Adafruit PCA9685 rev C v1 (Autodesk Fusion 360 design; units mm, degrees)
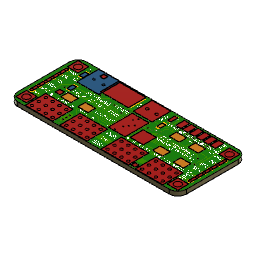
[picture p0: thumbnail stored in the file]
part number: PCA9685
part number: 10K
part number: MOUNTINGHOLE2.5
part number: FIDUCIAL""
part number: AOD417
part number: GREEN
part number: 470
pcb "PCB1" BoardHeight 1.57
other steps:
extrude "Extrude1" new body sketch "Sketch1" along normal blind 1.57 bodies "Board"
extrude "Extrude1" new body sketch "Sketch1" along normal blind 0.1 bodies "TSSOP28"
extrude "Extrude1" new body sketch "Sketch1" along normal blind 0.1 bodies "SOLDERJUMPER_REFLOW_NOPASTE"
extrude "Extrude1" new body sketch "Sketch1" along normal blind 0.1 bodies "0805-NO"
extrude "Extrude1" new body sketch "Sketch1" along normal blind 0.1 bodies "TERMBLOCK_1X2-3.5MM"
extrude "Extrude1" new body sketch "Sketch1" along normal blind 0.1 bodies "MOUNTINGHOLE_2.5_PLATED"
extrude "Extrude1" new body sketch "Sketch1" along normal blind 0.1 bodies "FIDUCIAL_1MM"
extrude "Extrude1" new body sketch "Sketch1" along normal blind 0.1 bodies "TO252"
extrude "Extrude1" new body sketch "Sketch1" along normal blind 0.1 bodies "CHIPLED_0805_NOOUTLINE"
extrude "Extrude1" new body sketch "Sketch1" along normal blind 0.1 bodies "_0805MP"
extrude "Extrude1" new body sketch "Sketch1" along normal blind 0.1 bodies "E3,5-8"
extrude "Extrude1" new body sketch "Sketch1" along normal blind 0.1 bodies "ADAFRUIT_5MM"
extrude "Extrude1" new body sketch "Sketch1" along normal blind 0.1 bodies "1X06-CLEANBIG"
extrude "Extrude1" new body sketch "Sketch1" along normal blind 0.1 bodies "3X04"
extrude "Extrude1" new body sketch "Sketch1" along normal blind 0.1 bodies "RESPACK_4X0603"
extrude "Extrude1" new body sketch "Sketch1" along normal blind 0.1 bodies "PCBFEAT-REV-040"
extrude "Extrude1" new body sketch "Sketch1" along normal blind 0.1 bodies "TESTPOINT_ROUND_1MM"
extrude "Extrude2" sketch "Sketch2" blind 1.57
create_component "CreateComponent1"
create_component "CreateComponent1"
sketch "Sketch1" plane through (0, 0, 0) normal (0, 0, 1) x axis (1, 0, 0)
  line L1 (-1.905, 15.748) -> (-1.905, -3.302)
  line L2 (57.15, 18.923) -> (1.27, 18.923)
  line L3 (60.325, -3.302) -> (60.325, 15.748)
  line L4 (1.27, -6.477) -> (57.15, -6.477)
  arc A1 centre (1.27, -3.302) radius 3.175 clockwise from (1.27, -6.477) to (-1.905, -3.302)
  arc A2 centre (1.27, 15.748) radius 3.175 clockwise from (-1.905, 15.748) to (1.27, 18.923)
  arc A3 centre (57.15, 15.748) radius 3.175 clockwise from (57.15, 18.923) to (60.325, 15.748)
  arc A4 centre (57.15, -3.302) radius 3.175 clockwise from (60.325, -3.302) to (57.15, -6.477)
canvas "Canvas1"
canvas "Canvas2"
sketch "Sketch2" plane through (0, 0, 0) normal (0, 0, 1) x axis (1, 0, 0)
  circle C1 centre (15.24, -2.54) radius 0.25
  circle C2 centre (15.24, -1.27) radius 0.25
  circle C3 centre (15.24, -3.81) radius 0.25
  circle C4 centre (4.953, 16.637) radius 0.197
  circle C5 centre (27.94, 2.667) radius 0.197
  circle C6 centre (33.655, 9.144) radius 0.197
  circle C7 centre (46.482, 13.081) radius 0.197
  circle C8 centre (5.334, 6.731) radius 0.197
  circle C9 centre (50.419, 14.224) radius 0.197
  circle C10 centre (29.083, 10.16) radius 0.197
  circle C11 centre (47.879, 14.224) radius 0.197
  circle C12 centre (24.765, 10.922) radius 0.197
  circle C13 centre (45.339, 14.224) radius 0.197
  circle C14 centre (22.86, 10.795) radius 0.197
  circle C15 centre (42.799, 14.224) radius 0.197
  circle C16 centre (23.876, 9.017) radius 0.197
  circle C17 centre (40.259, 14.224) radius 0.197
  circle C18 centre (20.193, 10.287) radius 0.197
  circle C19 centre (38.989, 14.605) radius 0.197
  circle C20 centre (15.367, 11.811) radius 0.197
  circle C21 centre (30.48, 7.493) radius 0.197
  circle C22 centre (29.464, 6.223) radius 0.197
  circle C23 centre (14.478, 10.795) radius 0.197
  circle C24 centre (52.578, 8.636) radius 0.197
  circle C25 centre (28.575, 5.08) radius 0.197
  circle C26 centre (28.321, 9.017) radius 0.197
  circle C27 centre (53.848, 6.096) radius 0.197
  circle C28 centre (27.41, 15.113) radius 0.5
  circle C29 centre (30.91, 15.113) radius 0.5
  circle C30 centre (1.27, 15.748) radius 1.25
  circle C31 centre (1.27, -3.302) radius 1.25
  circle C32 centre (57.15, 15.748) radius 1.25
  circle C33 centre (57.15, -3.302) radius 1.25
  circle C34 centre (8.128, 14.732) radius 0.4065
  circle C35 centre (11.684, 14.732) radius 0.4065
  circle C36 centre (0, 0) radius 0.508
  circle C37 centre (0, 2.54) radius 0.508
  circle C38 centre (0, 5.08) radius 0.508
  circle C39 centre (0, 7.62) radius 0.508
  circle C40 centre (0, 10.16) radius 0.508
  circle C41 centre (0, 12.7) radius 0.508
  circle C42 centre (58.42, 0) radius 0.508
  circle C43 centre (58.42, 2.54) radius 0.508
  circle C44 centre (58.42, 5.08) radius 0.508
  circle C45 centre (58.42, 7.62) radius 0.508
  circle C46 centre (58.42, 10.16) radius 0.508
  circle C47 centre (58.42, 12.7) radius 0.508
  circle C48 centre (25.4, 0) radius 0.5
  circle C49 centre (25.4, -2.54) radius 0.5
  circle C50 centre (22.86, 0) radius 0.5
  circle C51 centre (22.86, -2.54) radius 0.5
  circle C52 centre (20.32, 0) radius 0.5
  circle C53 centre (20.32, -2.54) radius 0.5
  circle C54 centre (17.78, 0) radius 0.5
  circle C55 centre (17.78, -2.54) radius 0.5
  circle C56 centre (25.4, -5.08) radius 0.5
  circle C57 centre (22.86, -5.08) radius 0.5
  circle C58 centre (20.32, -5.08) radius 0.5
  circle C59 centre (17.78, -5.08) radius 0.5
  circle C60 centre (12.7, 0) radius 0.5
  circle C61 centre (12.7, -2.54) radius 0.5
  circle C62 centre (10.16, 0) radius 0.5
  circle C63 centre (10.16, -2.54) radius 0.5
  circle C64 centre (7.62, 0) radius 0.5
  circle C65 centre (7.62, -2.54) radius 0.5
  circle C66 centre (5.08, 0) radius 0.5
  circle C67 centre (5.08, -2.54) radius 0.5
  circle C68 centre (12.7, -5.08) radius 0.5
  circle C69 centre (10.16, -5.08) radius 0.5
  circle C70 centre (7.62, -5.08) radius 0.5
  circle C71 centre (5.08, -5.08) radius 0.5
  circle C72 centre (53.34, 0) radius 0.5
  circle C73 centre (53.34, -2.54) radius 0.5
  circle C74 centre (50.8, 0) radius 0.5
  circle C75 centre (50.8, -2.54) radius 0.5
  circle C76 centre (48.26, 0) radius 0.5
  circle C77 centre (48.26, -2.54) radius 0.5
  circle C78 centre (45.72, 0) radius 0.5
  circle C79 centre (45.72, -2.54) radius 0.5
  circle C80 centre (53.34, -5.08) radius 0.5
  circle C81 centre (50.8, -5.08) radius 0.5
  circle C82 centre (48.26, -5.08) radius 0.5
  circle C83 centre (45.72, -5.08) radius 0.5
  circle C84 centre (40.64, 0) radius 0.5
  circle C85 centre (40.64, -2.54) radius 0.5
  circle C86 centre (38.1, 0) radius 0.5
  circle C87 centre (38.1, -2.54) radius 0.5
  circle C88 centre (35.56, 0) radius 0.5
  circle C89 centre (35.56, -2.54) radius 0.5
  circle C90 centre (33.02, 0) radius 0.5
  circle C91 centre (33.02, -2.54) radius 0.5
  circle C92 centre (40.64, -5.08) radius 0.5
  circle C93 centre (38.1, -5.08) radius 0.5
  circle C94 centre (35.56, -5.08) radius 0.5
  circle C95 centre (33.02, -5.08) radius 0.5
create_component "CreateComponent2" sketch "Sketch1"
sketch "Sketch1" plane through (0, 0, 0) normal (0, 0, 1) x axis (1, 0, 0)
  line L1 (4.465, -3.121) -> (-4.465, -3.121)
  line L2 (4.465, 3.121) -> (4.465, -3.121)
  line L3 (-4.465, 3.121) -> (4.465, 3.121)
  line L4 (-4.465, -3.121) -> (-4.465, 3.121)
create_component "CreateComponent3" sketch "Sketch1"
sketch "Sketch1" plane through (0, 0, 0) normal (0, 0, 1) x axis (1, 0, 0)
  line L1 (1.651, -1.016) -> (-1.651, -1.016)
  line L2 (1.651, 1.016) -> (1.651, -1.016)
  line L3 (-1.651, 1.016) -> (1.651, 1.016)
  line L4 (-1.651, -1.016) -> (-1.651, 1.016)
create_component "CreateComponent4" sketch "Sketch1"
sketch "Sketch1" plane through (0, 0, 0) normal (0, 0, 1) x axis (1, 0, 0)
  line L1 (1.106, -0.724) -> (-1.092, -0.724)
  line L2 (1.106, 0.726) -> (1.106, -0.724)
  line L3 (-1.092, 0.726) -> (1.106, 0.726)
  line L4 (-1.092, -0.724) -> (-1.092, 0.726)
create_component "CreateComponent5" sketch "Sketch1"
sketch "Sketch1" plane through (0, 0, 0) normal (0, 0, 1) x axis (1, 0, 0)
  line L1 (3.6, -3.6) -> (-3.4, -3.6)
  line L2 (3.6, 3.4) -> (3.6, -3.6)
  line L3 (-3.4, 3.4) -> (3.6, 3.4)
  line L4 (-3.4, -3.6) -> (-3.4, 3.4)
create_component "CreateComponent6" sketch "Sketch1"
sketch "Sketch1" plane through (0, 0, 0) normal (0, 0, 1) x axis (1, 0, 0)
  line L1 (2, -2) -> (-2, -2)
  line L2 (2, 2) -> (2, -2)
  line L3 (-2, 2) -> (2, 2)
  line L4 (-2, -2) -> (-2, 2)
create_component "CreateComponent7" sketch "Sketch1"
sketch "Sketch1" plane through (0, 0, 0) normal (0, 0, 1) x axis (1, 0, 0)
  line L1 (0.75, -0.75) -> (-0.75, -0.75)
  line L2 (0.75, 0.75) -> (0.75, -0.75)
  line L3 (-0.75, 0.75) -> (0.75, 0.75)
  line L4 (-0.75, -0.75) -> (-0.75, 0.75)
create_component "CreateComponent8" sketch "Sketch1"
sketch "Sketch1" plane through (0, 0, 0) normal (0, 0, 1) x axis (1, 0, 0)
  line L1 (3.277, -5.156) -> (-3.277, -5.156)
  line L2 (3.277, 5.105) -> (3.277, -5.156)
  line L3 (-3.277, 5.105) -> (3.277, 5.105)
  line L4 (-3.277, -5.156) -> (-3.277, 5.105)
create_component "CreateComponent9" sketch "Sketch1"
sketch "Sketch1" plane through (0, 0, 0) normal (0, 0, 1) x axis (1, 0, 0)
  line L1 (0.625, -1.3334) -> (-0.625, -1.3334)
  line L2 (0.625, 1.3334) -> (0.625, -1.3334)
  line L3 (-0.625, 1.3334) -> (0.625, 1.3334)
  line L4 (-0.625, -1.3334) -> (-0.625, 1.3334)
create_component "CreateComponent10" sketch "Sketch1"
sketch "Sketch1" plane through (0, 0, 0) normal (0, 0, 1) x axis (1, 0, 0)
  line L1 (1, -0.65) -> (-1, -0.65)
  line L2 (1, 0.65) -> (1, -0.65)
  line L3 (-1, 0.65) -> (1, 0.65)
  line L4 (-1, -0.65) -> (-1, 0.65)
create_component "CreateComponent11" sketch "Sketch1"
sketch "Sketch1" plane through (0, 0, 0) normal (0, 0, 1) x axis (1, 0, 0)
  line L1 (4.064, -4.064) -> (-4.064, -4.064)
  line L2 (4.064, 4.064) -> (4.064, -4.064)
  line L3 (-4.064, 4.064) -> (4.064, 4.064)
  line L4 (-4.064, -4.064) -> (-4.064, 4.064)
create_component "CreateComponent12" sketch "Sketch1"
sketch "Sketch1" plane through (0, 0, 0) normal (0, 0, 1) x axis (1, 0, 0)
  line L1 (4.873, -0.004) -> (-0.004, -0.004)
  line L2 (4.873, 4.865) -> (4.873, -0.004)
  line L3 (-0.004, 4.865) -> (4.873, 4.865)
  line L4 (-0.004, -0.004) -> (-0.004, 4.865)
create_component "CreateComponent13" sketch "Sketch1"
sketch "Sketch1" plane through (0, 0, 0) normal (0, 0, 1) x axis (1, 0, 0)
  line L1 (6.858, -0.508) -> (-6.858, -0.508)
  line L2 (6.858, 0.508) -> (6.858, -0.508)
  line L3 (-6.858, 0.508) -> (6.858, 0.508)
  line L4 (-6.858, -0.508) -> (-6.858, 0.508)
create_component "CreateComponent14" sketch "Sketch1"
sketch "Sketch1" plane through (0, 0, 0) normal (0, 0, 1) x axis (1, 0, 0)
  line L1 (5.08, -3.81) -> (-5.08, -3.81)
  line L2 (5.08, 3.81) -> (5.08, -3.81)
  line L3 (-5.08, 3.81) -> (5.08, 3.81)
  line L4 (-5.08, -3.81) -> (-5.08, 3.81)
create_component "CreateComponent15" sketch "Sketch1"
sketch "Sketch1" plane through (0, 0, 0) normal (0, 0, 1) x axis (1, 0, 0)
  line L1 (1.9, -1.4) -> (-1.9, -1.4)
  line L2 (1.9, 1.4) -> (1.9, -1.4)
  line L3 (-1.9, 1.4) -> (1.9, 1.4)
  line L4 (-1.9, -1.4) -> (-1.9, 1.4)
create_component "CreateComponent16" sketch "Sketch1"
sketch "Sketch1" plane through (0, 0, 0) normal (0, 0, 1) x axis (1, 0, 0)
  line L1 (0.898, -0.898) -> (-0.898, -0.898)
  line L2 (0.898, 0.898) -> (0.898, -0.898)
  line L3 (-0.898, 0.898) -> (0.898, 0.898)
  line L4 (-0.898, -0.898) -> (-0.898, 0.898)
create_component "CreateComponent17" sketch "Sketch1"
sketch "Sketch1" plane through (0, 0, 0) normal (0, 0, 1) x axis (1, 0, 0)
  line L1 (0.7, -0.7) -> (-0.7, -0.7)
  line L2 (0.7, 0.7) -> (0.7, -0.7)
  line L3 (-0.7, 0.7) -> (0.7, 0.7)
  line L4 (-0.7, -0.7) -> (-0.7, 0.7)
as_built_joint "As-built1"
named bodies: "Board", "TSSOP28", "SOLDERJUMPER_REFLOW_NOPASTE", "0805-NO", "TERMBLOCK_1X2-3.5MM", "MOUNTINGHOLE_2.5_PLATED", "FIDUCIAL_1MM", "TO252", "CHIPLED_0805_NOOUTLINE", "_0805MP", "E3,5-8", "ADAFRUIT_5MM", "1X06-CLEANBIG", "3X04", "RESPACK_4X0603", "PCBFEAT-REV-040", "TESTPOINT_ROUND_1MM"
